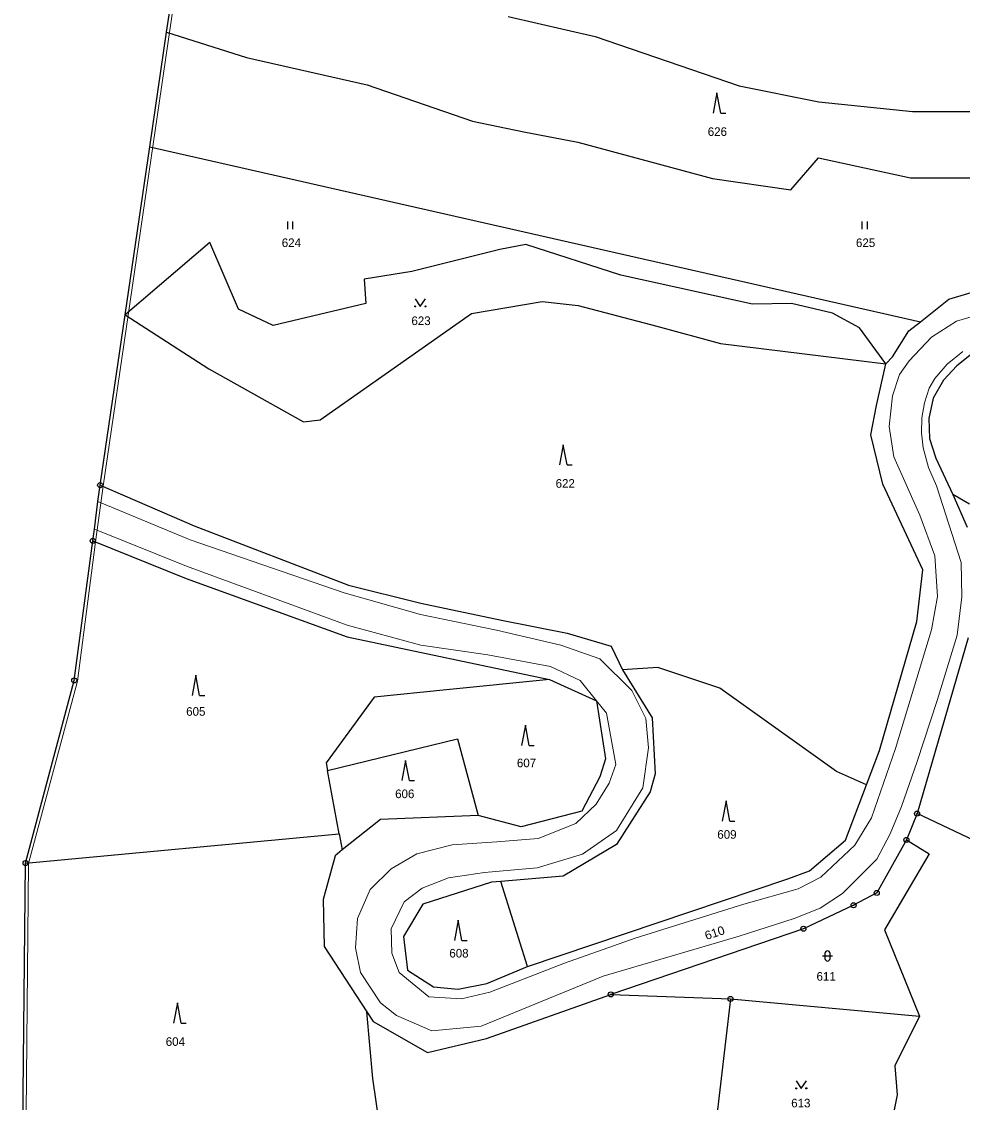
# Model space of a CAD drawing. Extents: x -653193 to -651624, y -1092017 to -1090260.
# Drawn here: x -653192.6 to -653007.1, y -1091249.7 to -1091036.5 of the extents above; entities that cross this region are included whole.
import ezdxf
from ezdxf.enums import TextEntityAlignment as Align

# ---------------------------------------------------------------- set-up
doc = ezdxf.new("R2010")
doc.units = 0
doc.header["$LTSCALE"] = 0.68
for name, color, linetype, lineweight in [('1', 7, 'Continuous', 25), ('3', 7, 'Continuous', 25), ('4', 7, 'Continuous', 13), ('8', 7, 'Continuous', 25)]:
    doc.layers.add(name, color=color, linetype=linetype, lineweight=lineweight)
doc.layers.add('2', color=7, linetype='Continuous')

msp = doc.modelspace()

# ---------------------------------------------------------------- linework, layer by layer
at = {"layer": '1'}
for p, q in [((-653164, -1091038.62), (-653162.28, -1091026.88)), ((-653096.62, -1091035.52), (-653079.47, -1091039.46)), ((-653167.31, -1091061.19), (-653164, -1091038.62)), ((-653164, -1091038.62), (-653148.27, -1091043.61)), ((-653079.47, -1091039.46), (-653051.08, -1091049.17)), ((-653148.27, -1091043.61), (-653124.43, -1091048.96)), ((-653124.43, -1091048.96), (-653103.68, -1091056.13)), ((-653051.08, -1091049.17), (-653035.36, -1091052.36)), ((-653035.36, -1091052.36), (-653016.89, -1091054.24)), ((-653016.89, -1091054.24), (-653000.41, -1091054.28)), ((-653103.68, -1091056.13), (-653093.57, -1091058.27)), ((-653093.57, -1091058.27), (-653082.94, -1091060.3)), ((-653172.18, -1091094.37), (-653167.31, -1091061.19)), ((-653167.31, -1091061.19), (-653015.32, -1091095.72)), ((-653082.94, -1091060.3), (-653056.36, -1091067.44)), ((-653040.88, -1091069.7), (-653035.45, -1091063.39)), ((-653035.45, -1091063.39), (-653017.28, -1091067.36)), ((-653056.36, -1091067.44), (-653040.88, -1091069.7)), ((-653017.28, -1091067.36), (-652995.19, -1091067.3)), ((-653155.5, -1091080.1), (-653172.18, -1091094.37)), ((-653149.82, -1091093.27), (-653155.5, -1091080.1)), ((-653093.16, -1091080.5), (-653098.26, -1091081.49)), ((-653074.43, -1091086.53), (-653093.16, -1091080.5)), ((-653098.26, -1091081.49), (-653115.62, -1091085.78)), ((-653115.62, -1091085.78), (-653125.05, -1091087.33)), ((-653125.05, -1091087.33), (-653124.69, -1091092.13)), ((-653048.44, -1091092.22), (-653074.43, -1091086.53)), ((-653009.73, -1091091.28), (-653001.98, -1091088.96)), ((-653103.88, -1091094.11), (-653089.92, -1091091.73)), ((-653089.92, -1091091.73), (-653082.82, -1091092.53)), ((-653015.32, -1091095.72), (-653009.73, -1091091.28)), ((-653143.01, -1091096.47), (-653149.82, -1091093.27)), ((-653124.69, -1091092.13), (-653143.01, -1091096.47)), ((-653082.82, -1091092.53), (-653067.31, -1091096.62)), ((-653040.75, -1091092.11), (-653048.44, -1091092.22)), ((-653032.68, -1091094.02), (-653040.75, -1091092.11)), ((-653177.11, -1091127.95), (-653172.18, -1091094.37)), ((-653172.18, -1091094.37), (-653155.67, -1091104.99)), ((-653133.75, -1091115.07), (-653103.88, -1091094.11)), ((-653027.39, -1091096.94), (-653032.68, -1091094.02)), ((-653017.61, -1091097.54), (-653015.32, -1091095.72)), ((-653067.31, -1091096.62), (-653054.76, -1091100.04)), ((-653022.18, -1091104.03), (-653027.39, -1091096.94)), ((-653020.84, -1091102.64), (-653017.61, -1091097.54)), ((-653054.76, -1091100.04), (-653022.18, -1091104.03)), ((-653004.94, -1091101.86), (-653008.17, -1091104.44)), ((-653024.03, -1091112.26), (-653022.18, -1091104.03)), ((-653022.18, -1091104.03), (-653020.84, -1091102.64)), ((-653008.17, -1091104.44), (-653010.82, -1091107.24)), ((-653155.67, -1091104.99), (-653137.04, -1091115.46)), ((-653010.82, -1091107.24), (-653012.86, -1091110.77)), ((-653012.86, -1091110.77), (-653013.7, -1091114.79)), ((-653025.1, -1091118.01), (-653024.03, -1091112.26)), ((-653137.04, -1091115.46), (-653133.75, -1091115.07)), ((-653013.7, -1091114.79), (-653013.54, -1091118.77)), ((-653022.75, -1091127.75), (-653025.1, -1091118.01)), ((-653013.54, -1091118.77), (-653012.3, -1091122.63)), ((-653012.3, -1091122.63), (-653008.93, -1091129.81)), ((-653177.54, -1091131.2), (-653177.11, -1091127.95)), ((-653177.11, -1091127.95), (-653158.6, -1091136.01)), ((-653014.87, -1091144.63), (-653022.75, -1091127.75)), ((-653178.26, -1091136.61), (-653177.54, -1091131.2)), ((-653158.6, -1091136.01), (-653128.16, -1091147.71)), ((-653178.57, -1091138.93), (-653178.26, -1091136.61)), ((-653182.23, -1091166.46), (-653178.57, -1091138.93)), ((-653178.57, -1091138.93), (-653160.15, -1091146.34)), ((-653016.06, -1091154.84), (-653014.87, -1091144.63)), ((-653160.15, -1091146.34), (-653128.38, -1091157.89)), ((-653128.16, -1091147.71), (-653113.89, -1091151.23)), ((-653113.89, -1091151.23), (-653097.96, -1091154.56)), ((-653097.96, -1091154.56), (-653085.04, -1091157.12)), ((-653023.41, -1091180.32), (-653016.06, -1091154.84)), ((-653085.04, -1091157.12), (-653076.33, -1091159.73)), ((-653128.38, -1091157.89), (-653088.51, -1091166.29)), ((-653076.33, -1091159.73), (-653074.1, -1091164.4)), ((-653005.94, -1091158.08), (-653016, -1091192.75)), ((-653067.1, -1091163.94), (-653074.1, -1091164.4)), ((-653054.93, -1091168.02), (-653067.1, -1091163.94)), ((-653088.51, -1091166.29), (-653108.79, -1091168.35)), ((-653088.51, -1091166.29), (-653079.21, -1091170.52)), ((-653074.1, -1091164.4), (-653068.24, -1091173.83)), ((-653191.83, -1091202.49), (-653182.23, -1091166.46)), ((-653108.79, -1091168.35), (-653123.1, -1091169.8)), ((-653031.92, -1091184.47), (-653054.93, -1091168.02)), ((-653123.1, -1091169.8), (-653132.57, -1091182.76)), ((-653079.21, -1091170.52), (-653077.48, -1091181.94)), ((-653068.24, -1091173.83), (-653067.64, -1091184.87)), ((-653132.29, -1091184.27), (-653106.64, -1091178.01)), ((-653106.64, -1091178.01), (-653102.57, -1091193.13)), ((-653025.98, -1091187.09), (-653023.41, -1091180.32)), ((-653132.57, -1091182.76), (-653132.29, -1091184.27)), ((-653077.48, -1091181.94), (-653078.55, -1091185.48)), ((-653129.99, -1091196.73), (-653132.29, -1091184.27)), ((-653078.55, -1091185.48), (-653082.15, -1091192.25)), ((-653067.64, -1091184.87), (-653068.63, -1091188.43)), ((-653025.98, -1091187.09), (-653031.92, -1091184.47)), ((-653030.11, -1091197.96), (-653025.98, -1091187.09)), ((-653068.63, -1091188.43), (-653075.28, -1091198.82)), ((-653121.8, -1091193.94), (-653129.41, -1091199.87)), ((-653102.57, -1091193.13), (-653121.8, -1091193.94)), ((-653094.08, -1091195.36), (-653102.57, -1091193.13)), ((-653082.15, -1091192.25), (-653094.08, -1091195.36)), ((-653016, -1091192.75), (-653018.1, -1091197.94)), ((-653000.66, -1091199.98), (-653016, -1091192.75)), ((-653191.83, -1091202.49), (-653129.99, -1091196.73)), ((-653129.99, -1091196.73), (-653129.41, -1091199.87)), ((-653037.24, -1091204.01), (-653030.11, -1091197.96)), ((-653018.1, -1091197.94), (-653023.97, -1091208.4)), ((-653018.1, -1091197.94), (-653013.59, -1091200.71)), ((-653129.41, -1091199.87), (-653130.74, -1091201.08)), ((-653075.28, -1091198.82), (-653085.83, -1091205.08)), ((-653192.6, -1091279.83), (-653191.83, -1091202.49)), ((-653130.74, -1091201.08), (-653133.15, -1091209.72)), ((-653013.59, -1091200.71), (-653022.46, -1091215.68)), ((-653041.5, -1091205.64), (-653037.24, -1091204.01)), ((-653099.94, -1091206.29), (-653113.5, -1091210.58)), ((-653098.07, -1091206.13), (-653099.94, -1091206.29)), ((-653085.83, -1091205.08), (-653098.07, -1091206.13)), ((-653092.83, -1091222.93), (-653098.07, -1091206.13)), ((-653092.83, -1091222.93), (-653041.5, -1091205.64)), ((-653023.97, -1091208.4), (-653028.52, -1091210.82)), ((-653133.15, -1091209.72), (-653132.93, -1091218.98)), ((-653113.5, -1091210.58), (-653117.27, -1091217.02)), ((-653028.52, -1091210.82), (-653038.42, -1091215.46)), ((-653117.27, -1091217.02), (-653116.51, -1091223.65)), ((-653038.42, -1091215.46), (-653076.41, -1091228.41)), ((-653022.46, -1091215.68), (-653015.54, -1091232.69)), ((-653132.93, -1091218.98), (-653124.53, -1091231.86)), ((-653116.51, -1091223.65), (-653111.4, -1091226.91)), ((-653100.83, -1091226.24), (-653092.83, -1091222.93)), ((-653111.4, -1091226.91), (-653106.48, -1091227.35)), ((-653106.48, -1091227.35), (-653100.83, -1091226.24)), ((-653100.93, -1091237.1), (-653076.41, -1091228.41)), ((-653076.41, -1091228.41), (-653052.81, -1091229.31)), ((-653052.81, -1091229.31), (-653057.71, -1091270.93)), ((-653052.81, -1091229.31), (-653015.54, -1091232.69)), ((-653124.53, -1091231.86), (-653123.28, -1091233.78)), ((-653123.34, -1091244.98), (-653124.53, -1091231.86)), ((-653123.28, -1091233.78), (-653112.58, -1091239.89)), ((-653015.54, -1091232.69), (-653020.42, -1091242.51)), ((-653112.58, -1091239.89), (-653100.93, -1091237.1)), ((-653020.42, -1091242.51), (-653019.92, -1091248.19)), ((-653120.1, -1091266.89), (-653123.34, -1091244.98)), ((-653019.92, -1091248.19), (-653021.65, -1091256.78))]:
    msp.add_line(p, q, dxfattribs=at)
msp.add_lwpolyline([(-653005.69, -1091131.68), (-653008.93, -1091129.81), (-653006.14, -1091136.24)], dxfattribs=at)
at = {"layer": '3'}
for p, q in [((-653054.72, -1091054.58), (-653053.724, -1091054.58)), ((-653140.111, -1091077.43), (-653140.111, -1091075.93)), ((-653139.11, -1091077.43), (-653139.11, -1091075.93)), ((-653026.811, -1091077.46), (-653026.811, -1091075.96)), ((-653025.81, -1091077.46), (-653025.81, -1091075.96)), ((-653085.04, -1091123.97), (-653084.044, -1091123.97)), ((-653157.49, -1091169.43), (-653156.494, -1091169.43)), ((-653092.51, -1091179.3), (-653091.514, -1091179.3)), ((-653116.12, -1091186.24), (-653115.124, -1091186.24)), ((-653052.93, -1091194.22), (-653051.934, -1091194.22)), ((-653105.76, -1091217.75), (-653104.764, -1091217.75)), ((-653034.671, -1091220.821), (-653032.669, -1091220.821)), ((-653034.171, -1091220.321), (-653034.171, -1091221.322)), ((-653033.169, -1091221.322), (-653033.169, -1091220.321)), ((-653161.13, -1091234.06), (-653160.134, -1091234.06))]:
    msp.add_line(p, q, dxfattribs=at)
for points in [[(-653054.72, -1091054.58), (-653055.47, -1091050.58), (-653056.22, -1091054.58)], [(-653114.97, -1091091.189), (-653113.97, -1091092.69), (-653112.97, -1091091.189)], [(-653085.04, -1091123.97), (-653085.79, -1091119.97), (-653086.54, -1091123.97)], [(-653157.49, -1091169.43), (-653158.24, -1091165.43), (-653158.99, -1091169.43)], [(-653092.51, -1091179.3), (-653093.26, -1091175.3), (-653094.01, -1091179.3)], [(-653116.12, -1091186.24), (-653116.87, -1091182.24), (-653117.62, -1091186.24)], [(-653052.93, -1091194.22), (-653053.68, -1091190.22), (-653054.43, -1091194.22)], [(-653105.76, -1091217.75), (-653106.51, -1091213.75), (-653107.26, -1091217.75)], [(-653161.13, -1091234.06), (-653161.88, -1091230.06), (-653162.63, -1091234.06)], [(-653039.84, -1091245.439), (-653038.84, -1091246.94), (-653037.84, -1091245.439)]]:
    msp.add_lwpolyline(points, dxfattribs=at)
for centre in [(-653114.97, -1091092.6895), (-653112.97, -1091092.6895), (-653039.84, -1091246.9395), (-653037.84, -1091246.9395)]:
    msp.add_circle(centre, 0.1, dxfattribs=at)
for centre, start, end in [((-653033.67, -1091220.3209), 0, 180), ((-653033.67, -1091221.3209), 180, 359.98789)]:
    msp.add_arc(centre, 0.5, start, end, dxfattribs=at)
at = {"layer": '4'}
for p, q in [((-653008.25, -1091095.61), (-653013.14, -1091098.74)), ((-653002.66, -1091093.97), (-653008.25, -1091095.61)), ((-653013.14, -1091098.74), (-653017.55, -1091103.42)), ((-653010.08, -1091104.07), (-653006.96, -1091101.6)), ((-653017.55, -1091103.42), (-653019.47, -1091106.11)), ((-653012.47, -1091106.92), (-653010.08, -1091104.07)), ((-653020.87, -1091110.33), (-653019.47, -1091106.11)), ((-653013.63, -1091108.85), (-653012.47, -1091106.92)), ((-653021.51, -1091116.39), (-653020.87, -1091110.33)), ((-653014.54, -1091111.72), (-653013.63, -1091108.85)), ((-653015.04, -1091114.66), (-653014.54, -1091111.72)), ((-653015.14, -1091117.64), (-653015.04, -1091114.66)), ((-653020.56, -1091122.38), (-653021.51, -1091116.39)), ((-653014.81, -1091120.62), (-653015.14, -1091117.64)), ((-653013.74, -1091124.44), (-653014.81, -1091120.62)), ((-653015.46, -1091133.86), (-653020.56, -1091122.38)), ((-653012.17, -1091128.1), (-653013.74, -1091124.44)), ((-653007.34, -1091143.21), (-653012.17, -1091128.1)), ((-653177.54, -1091131.2), (-653159.36, -1091138.75)), ((-653012.51, -1091141.89), (-653015.46, -1091133.86)), ((-653178.26, -1091136.61), (-653160.06, -1091143.93)), ((-653159.36, -1091138.75), (-653128.97, -1091149.18)), ((-653011.97, -1091149.94), (-653012.51, -1091141.89)), ((-653160.06, -1091143.93), (-653128.38, -1091155.56)), ((-653007.18, -1091149.99), (-653007.34, -1091143.21)), ((-653128.97, -1091149.18), (-653113.91, -1091153.44)), ((-653013.16, -1091156.48), (-653011.97, -1091149.94)), ((-653008.12, -1091157.56), (-653007.18, -1091149.99)), ((-653113.91, -1091153.44), (-653098.97, -1091156.55)), ((-653128.38, -1091155.56), (-653113.89, -1091159.51)), ((-653098.97, -1091156.55), (-653086.29, -1091159.49)), ((-653020.23, -1091179.93), (-653013.16, -1091156.48)), ((-653012.06, -1091170.45), (-653008.12, -1091157.56)), ((-653113.89, -1091159.51), (-653100.66, -1091161.42)), ((-653086.29, -1091159.49), (-653078.55, -1091162.23)), ((-653100.66, -1091161.42), (-653088.28, -1091163.73)), ((-653088.28, -1091163.73), (-653082.46, -1091166.51)), ((-653072.29, -1091168.46), (-653078.55, -1091162.23)), ((-653082.46, -1091166.51), (-653079.21, -1091170.52)), ((-653069.48, -1091173.99), (-653072.29, -1091168.46)), ((-653079.21, -1091170.52), (-653077.26, -1091172.92)), ((-653016, -1091182.47), (-653012.06, -1091170.45)), ((-653077.26, -1091172.92), (-653075.39, -1091183.05)), ((-653068.94, -1091179.79), (-653069.48, -1091173.99)), ((-653070.08, -1091187.69), (-653068.94, -1091179.79)), ((-653025.01, -1091193.61), (-653020.23, -1091179.93)), ((-653075.39, -1091183.05), (-653076.73, -1091186.77)), ((-653019.05, -1091191.33), (-653016, -1091182.47)), ((-653076.73, -1091186.77), (-653079.27, -1091190.9)), ((-653075.26, -1091196.07), (-653070.08, -1091187.69)), ((-653079.27, -1091190.9), (-653083.32, -1091194.69)), ((-653021.29, -1091196.76), (-653019.05, -1091191.33)), ((-653028.3, -1091198.97), (-653025.01, -1091193.61)), ((-653090.75, -1091197.65), (-653083.32, -1091194.69)), ((-653075.26, -1091196.07), (-653081.97, -1091200.74)), ((-653107.68, -1091198.88), (-653098.89, -1091198.34)), ((-653098.89, -1091198.34), (-653090.75, -1091197.65)), ((-653023.95, -1091201.73), (-653021.29, -1091196.76)), ((-653114.66, -1091200.68), (-653107.68, -1091198.88)), ((-653034.99, -1091205.3), (-653028.3, -1091198.97)), ((-653119.7, -1091203.62), (-653114.66, -1091200.68)), ((-653081.97, -1091200.74), (-653090.94, -1091203.43)), ((-653030.74, -1091208.5), (-653023.95, -1091201.73)), ((-653123.83, -1091207.74), (-653119.7, -1091203.62)), ((-653101.32, -1091204.38), (-653108.42, -1091205.42)), ((-653090.94, -1091203.43), (-653101.32, -1091204.38)), ((-653108.42, -1091205.42), (-653113.59, -1091207.42)), ((-653039.44, -1091207.57), (-653034.99, -1091205.3)), ((-653126.37, -1091213.46), (-653123.83, -1091207.74)), ((-653113.59, -1091207.42), (-653117.14, -1091210.14)), ((-653050.2, -1091210.61), (-653039.44, -1091207.57)), ((-653035.1, -1091211.38), (-653030.74, -1091208.5)), ((-653117.14, -1091210.14), (-653119.73, -1091215.46)), ((-653071.58, -1091217.32), (-653050.2, -1091210.61)), ((-653040.27, -1091213.46), (-653035.1, -1091211.38)), ((-653126.78, -1091219.22), (-653126.37, -1091213.46)), ((-653051.11, -1091216.9), (-653040.27, -1091213.46)), ((-653119.73, -1091215.46), (-653119.62, -1091220.27)), ((-653085.55, -1091222.27), (-653071.58, -1091217.32)), ((-653077.94, -1091224.83), (-653051.11, -1091216.9)), ((-653125.77, -1091224.06), (-653126.78, -1091219.22)), ((-653119.62, -1091220.27), (-653118.15, -1091224.12)), ((-653100.29, -1091228), (-653085.55, -1091222.27)), ((-653121.83, -1091230.06), (-653125.77, -1091224.06)), ((-653118.15, -1091224.12), (-653112.27, -1091228.92)), ((-653101.95, -1091234.69), (-653077.94, -1091224.83)), ((-653105.85, -1091229.31), (-653100.29, -1091228)), ((-653118.66, -1091232.6), (-653121.83, -1091230.06)), ((-653112.27, -1091228.92), (-653105.85, -1091229.31)), ((-653111.67, -1091235.57), (-653118.66, -1091232.6)), ((-653101.95, -1091234.69), (-653111.67, -1091235.57))]:
    msp.add_line(p, q, dxfattribs=at)
msp.add_lwpolyline([(-653150.38, -1090948.47), (-653165.77, -1090979.18), (-653165.35, -1091011.56), (-653161.74, -1091026.92), (-653176.52, -1091128.14), (-653178.05, -1091139.13), (-653181.58, -1091166.64), (-653191.27, -1091202.57), (-653191.99, -1091279.86), (-653185.4, -1091322.52), (-653167.88, -1091342.01), (-653153.56, -1091372.39), (-653125.53, -1091427.08), (-653100.42, -1091487.61), (-653082.33, -1091581.28), (-653077.75, -1091583), (-653070.49, -1091617.25)], dxfattribs=at)
at = {"layer": '8'}
for centre, radius in [((-653177.11, -1091127.9499), 0.5), ((-653177.11, -1091127.9499), 0.0303), ((-653178.57, -1091138.9299), 0.5), ((-653178.57, -1091138.9299), 0.0303), ((-653182.23, -1091166.4599), 0.5), ((-653182.23, -1091166.4599), 0.0303), ((-653016, -1091192.7499), 0.5), ((-653016, -1091192.7499), 0.0303), ((-653018.1, -1091197.9399), 0.5), ((-653018.1, -1091197.9399), 0.0303), ((-653191.83, -1091202.4899), 0.5), ((-653191.83, -1091202.4899), 0.0303), ((-653023.97, -1091208.3999), 0.5), ((-653023.97, -1091208.3999), 0.0303), ((-653028.52, -1091210.8199), 0.5), ((-653028.52, -1091210.8199), 0.0303), ((-653038.42, -1091215.4599), 0.5), ((-653038.42, -1091215.4599), 0.0303), ((-653076.41, -1091228.4099), 0.5), ((-653076.41, -1091228.4099), 0.0303), ((-653052.81, -1091229.3099), 0.5), ((-653052.81, -1091229.3099), 0.0303)]:
    msp.add_circle(centre, radius, dxfattribs=at)

# ---------------------------------------------------------------- texts
at = {"layer": '2'}
for s, p in [('626', (-653055.389, -1091059.065)), ('624', (-653139.399, -1091080.985)), ('625', (-653026.159, -1091080.985)), ('623', (-653113.829, -1091096.375)), ('622', (-653085.389, -1091128.465)), ('605', (-653158.249, -1091173.445)), ('607', (-653093.029, -1091183.595)), ('606', (-653117.039, -1091189.695)), ('609', (-653053.499, -1091197.705)), ('608', (-653106.349, -1091221.135)), ('611', (-653033.939, -1091225.705)), ('604', (-653162.279, -1091238.565)), ('613', (-653038.929, -1091250.695))]:
    msp.add_text(s, height=1.7, dxfattribs=at).set_placement(p, align=Align.CENTER)
at = {"layer": '2', "width": 1.05}
msp.add_text('610', height=1.7, rotation=18, dxfattribs=at).set_placement((-653055.6647, -1091217.0701), align=Align.CENTER)

doc.saveas('drawing.dxf')
